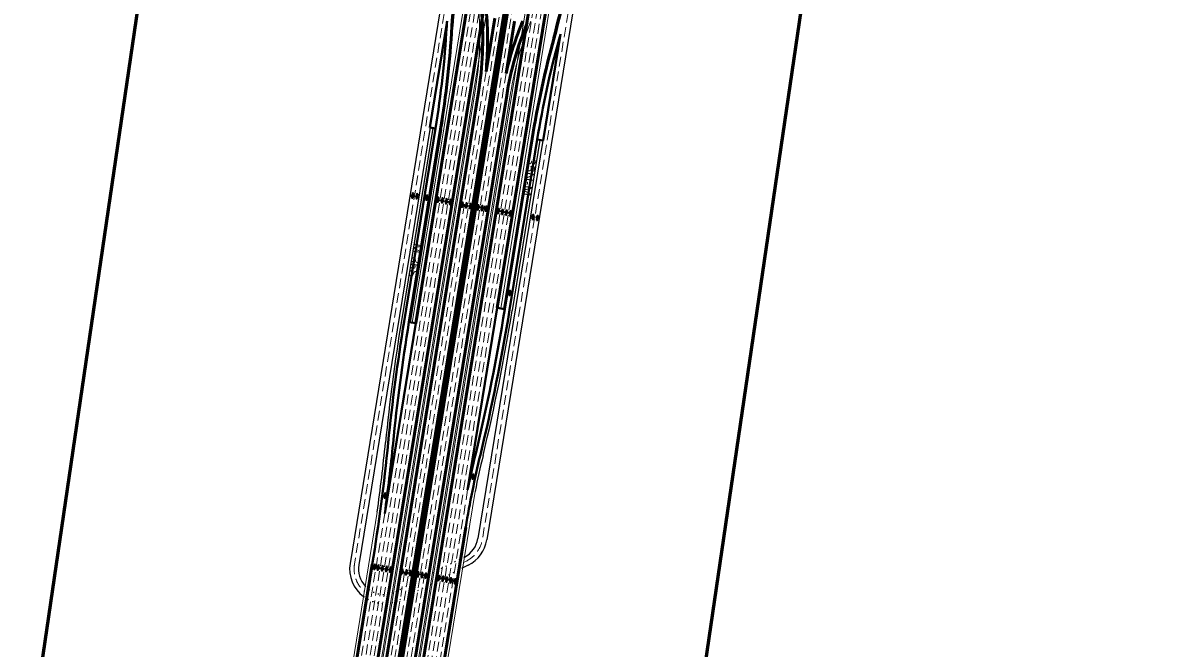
# Model space of a CAD drawing. Extents: x 2329387 to 2347382, y 6951580 to 6987999.
# Drawn here: x 2331839 to 2335155, y 6980657 to 6982469 of the extents above; entities that cross this region are included whole.
import ezdxf

# ---------------------------------------------------------------- set-up
doc = ezdxf.new("R2010")
doc.units = 0
doc.header["$LTSCALE"] = 9.6
doc.linetypes.add('DOTTED', pattern=[1.5, 0.3, -1.2])
doc.linetypes.add('MEDIUM_DASHED', pattern=[4.5, 3, -1.5])
for name, color, linetype, lineweight in [('26', 7, 'Continuous', 53), ('27', 7, 'Continuous', 40), ('28', 7, 'Continuous', 25), ('30', 7, 'Continuous', 13), ('31', 7, 'Continuous', 53), ('41', 7, 'Continuous', 35), ('50', 7, 'MEDIUM_DASHED', 13), ('62', 7, 'Continuous', 60)]:
    doc.layers.add(name, color=color, linetype=linetype, lineweight=lineweight)
doc.layers.add('40', color=7, linetype='Continuous')

msp = doc.modelspace()

# ---------------------------------------------------------------- linework, layer by layer
at = {"layer": '26'}
for p, q in [((2333226.175, 6982836.253), (2332841.664, 6980470.76)), ((2333178.797, 6982843.954), (2332976.382, 6981598.707)), ((2333326.427, 6982642.749), (2332969.98, 6980449.902)), ((2333373.805, 6982635.048), (2333212.588, 6981643.246)), ((2333121.454, 6981007.799), (2333029.203, 6980440.276)), ((2332850.665, 6980900.096), (2332782.442, 6980480.387))]:
    msp.add_line(p, q, dxfattribs=at)
at = {"layer": '26', "lineweight": 13}
for p, q in [((2333236.045, 6982834.649), (2332851.535, 6980469.155)), ((2333168.926, 6982845.559), (2332966.511, 6981600.312)), ((2333316.556, 6982644.353), (2332960.11, 6980451.507)), ((2333383.672, 6982633.418), (2333222.458, 6981641.641)), ((2333148.472, 6981111.689), (2333039.073, 6980438.671)), ((2332865.065, 6981051.01), (2332772.571, 6980481.991))]:
    msp.add_line(p, q, dxfattribs=at)
at = {"layer": '27'}
for p, q in [((2333067.062, 6982474.436), (2333016.95, 6982166.149)), ((2333395.235, 6982436.552), (2333345.123, 6982128.265)), ((2333033.73, 6982163.421), (2332942.822, 6981604.163)), ((2333047.548, 6982161.175), (2332956.641, 6981601.916)), ((2333033.73, 6982163.421), (2333016.95, 6982166.149)), ((2333314.525, 6982133.238), (2333234.303, 6981639.716)), ((2333328.344, 6982130.992), (2333248.122, 6981637.47)), ((2333328.344, 6982130.992), (2333345.123, 6982128.265)), ((2333212.588, 6981643.246), (2333126.823, 6981115.624)), ((2333234.303, 6981639.716), (2333212.588, 6981643.246)), ((2332976.382, 6981598.707), (2332886.827, 6981047.767)), ((2332976.382, 6981598.707), (2332956.641, 6981601.916))]:
    msp.add_line(p, q, dxfattribs=at)
at = {"layer": '27', "lineweight": 25}
for p, q in [((2333025.833, 6982164.705), (2332934.926, 6981605.446)), ((2333051.497, 6982160.533), (2332960.589, 6981601.274)), ((2333310.577, 6982133.88), (2333230.355, 6981640.358)), ((2333336.24, 6982129.709), (2333256.018, 6981636.186))]:
    msp.add_line(p, q, dxfattribs=at)
at = {"layer": '27'}
for centre, radius, start, end in [((2335926.305, 6982296.254), 2850.789, 170.76734, 176.73017), ((2330626.764, 6983173.154), 2850.789, 344.8045, 350.76734), ((2330206.054, 6982623.059), 2864.789, 350.76734, 356.73017), ((2330206.054, 6982623.059), 2878.789, 350.76734, 356.73017), ((2335926.305, 6982296.254), 2864.789, 176.43406, 176.73018), ((2336156.019, 6981671.354), 2878.789, 164.8045, 170.76734), ((2336156.019, 6981671.354), 2864.789, 164.8045, 170.76734), ((2330626.764, 6983173.154), 2864.789, 344.8045, 345.10061), ((2327592.77, 6982556.746), 5715.578, 346.48444, 350.76734), ((2327592.77, 6982556.746), 5729.578, 346.48444, 350.76734), ((2338598.173, 6980684.887), 5729.578, 170.76734, 174.31827), ((2338598.173, 6980684.887), 5715.578, 170.76734, 174.31827), ((2327195.314, 6981819.372), 5729.578, 350.76734, 354.31827), ((2327195.314, 6981819.372), 5743.578, 352.27941, 354.31827), ((2335949.129, 6980548.161), 2864.789, 166.48444, 170.76734), ((2335949.129, 6980548.161), 2878.789, 166.48444, 168.63147)]:
    msp.add_arc(centre, radius, start, end, dxfattribs=at)
at = {"layer": '27', "lineweight": 25}
for centre, radius, start, end in [((2335926.305, 6982296.254), 2846.789, 170.76734, 176.73017), ((2330626.764, 6983173.154), 2846.789, 344.8045, 350.76734), ((2330206.054, 6982623.059), 2882.789, 350.76734, 356.73017), ((2336156.019, 6981671.354), 2882.789, 164.8045, 170.76734), ((2327592.77, 6982556.746), 5737.578, 346.48444, 350.76734), ((2338598.173, 6980684.887), 5737.578, 170.76734, 174.31827), ((2327195.314, 6981819.372), 5721.578, 352.28232, 354.31827), ((2335949.129, 6980548.161), 2856.789, 166.48444, 168.62327)]:
    msp.add_arc(centre, radius, start, end, dxfattribs=at)
at = {"layer": '28'}
for p, q in [((2333094.181, 6982797.091), (2332786.266, 6980902.809)), ((2333471.999, 6982752.984), (2333182.352, 6980971.084)), ((2333017.937, 6982165.988), (2332811.93, 6980898.638)), ((2333344.136, 6982128.425), (2333156.689, 6980975.255)), ((2333128.737, 6980897.871), (2333112.372, 6980889.604))]:
    msp.add_line(p, q, dxfattribs=at)
at = {"layer": '28', "linetype": 'DOTTED'}
for p, q in [((2333117.013, 6980921.077), (2332916.13, 6980819.598)), ((2333112.372, 6980889.604), (2332930.06, 6980797.507)), ((2332918.335, 6980820.713), (2332941.516, 6980832.423))]:
    msp.add_line(p, q, dxfattribs=at)
at = {"layer": '28'}
for centre, radius, start, end in [((2333083.647, 6980987.128), 74, 297.25103, 350.76734), ((2333083.647, 6980987.128), 100, 296.80123, 350.76734), ((2332884.971, 6980886.764), 100, 170.76734, 233.38023), ((2332884.971, 6980886.764), 74, 170.76656, 222.33268)]:
    msp.add_arc(centre, radius, start, end, dxfattribs=at)
at = {"layer": '28', "linetype": 'DOTTED'}
for centre, radius, start, end in [((2333077.645, 6980955.417), 74, 296.80014, 297.25102), ((2332884.971, 6980886.764), 74, 222.33269, 296.79976), ((2332884.971, 6980886.764), 100, 233.38023, 296.80123)]:
    msp.add_arc(centre, radius, start, end, dxfattribs=at)
at = {"layer": '30', "lineweight": 53}
for p, q in [((2333271.366, 6982740.303), (2332900.887, 6980461.133)), ((2333281.236, 6982738.699), (2332910.757, 6980459.529))]:
    msp.add_line(p, q, dxfattribs=at)
at = {"layer": '30'}
for p, q in [((2333275.314, 6982739.661), (2332904.835, 6980460.492)), ((2333277.288, 6982739.341), (2332906.809, 6980460.171))]:
    msp.add_line(p, q, dxfattribs=at)
at = {"layer": '31'}
for p, q in [((2333205.301, 6982483.463), (2333180.043, 6982328.074)), ((2333262.55, 6982474.157), (2333237.926, 6982322.673)), ((2333158.215, 6982268.582), (2332865.353, 6980466.909)), ((2333239.787, 6982259.33), (2332946.291, 6980453.753))]:
    msp.add_line(p, q, dxfattribs=at)
at = {"layer": '31', "lineweight": 13}
for p, q in [((2333149.671, 6982278.347), (2332855.483, 6980468.514)), ((2333251.033, 6982266.189), (2332956.162, 6980452.148))]:
    msp.add_line(p, q, dxfattribs=at)
for centre, radius, start, end in [((2334182.346, 6982106.118), 972.93, 157.63695, 157.63695), ((2332215.009, 6982430.276), 946.93, 350.76734, 4.36603), ((2334185.695, 6982114.26), 946.93, 157.63695, 170.76734)]:
    msp.add_arc(centre, radius, start, end, dxfattribs=at)
at = {"layer": '31'}
for centre, radius, start, end in [((2332215.656, 6982421.795), 954.93, 350.76734, 4.36603), ((2332215.656, 6982421.795), 968.93, 354.44931, 4.36603), ((2334182.346, 6982106.118), 968.93, 157.63695, 167.08536), ((2334182.346, 6982106.118), 954.93, 157.63695, 170.76734)]:
    msp.add_arc(centre, radius, start, end, dxfattribs=at)
at = {"layer": '41'}
for points in [[(2332970.135, 6981975.177), (2332967.179, 6981975.691), (2332966.012, 6981968.985), (2332963.611, 6981969.403), (2332966.1, 6981961.662), (2332971.057, 6981968.108), (2332968.969, 6981968.471)], [(2332982.783, 6981973.463), (2332979.826, 6981973.977), (2332978.66, 6981967.271), (2332976.258, 6981967.689), (2332978.747, 6981959.948), (2332983.704, 6981966.394), (2332981.616, 6981966.757)], [(2333011.015, 6981968.985), (2333008.059, 6981969.5), (2333006.892, 6981962.794), (2333004.491, 6981963.212), (2333006.979, 6981955.47), (2333011.936, 6981961.916), (2333009.848, 6981962.279)], [(2333043.591, 6981962.973), (2333040.635, 6981963.487), (2333039.468, 6981956.781), (2333037.067, 6981957.199), (2333039.555, 6981949.458), (2333044.512, 6981955.904), (2333042.424, 6981956.267)], [(2333055.815, 6981960.975), (2333052.859, 6981961.489), (2333051.692, 6981954.783), (2333049.291, 6981955.201), (2333051.78, 6981947.46), (2333056.737, 6981953.905), (2333054.648, 6981954.269)], [(2333067.734, 6981958.8), (2333064.778, 6981959.315), (2333063.611, 6981952.609), (2333061.21, 6981953.027), (2333063.698, 6981945.285), (2333068.655, 6981951.731), (2333066.567, 6981952.094)], [(2333079.305, 6981956.974), (2333076.349, 6981957.488), (2333075.182, 6981950.782), (2333072.781, 6981951.2), (2333075.269, 6981943.459), (2333080.226, 6981949.905), (2333078.138, 6981950.268)], [(2333113.633, 6981948.572), (2333110.676, 6981949.086), (2333109.51, 6981942.38), (2333107.108, 6981942.798), (2333109.597, 6981935.057), (2333114.554, 6981941.503), (2333112.466, 6981941.866)], [(2333125.812, 6981946.659), (2333122.856, 6981947.173), (2333121.689, 6981940.467), (2333119.288, 6981940.885), (2333121.777, 6981933.143), (2333126.734, 6981939.589), (2333124.646, 6981939.953)], [(2333137.25, 6981944.888), (2333134.293, 6981945.402), (2333133.127, 6981938.696), (2333130.725, 6981939.114), (2333133.214, 6981931.372), (2333138.171, 6981937.818), (2333136.083, 6981938.182)], [(2333154.193, 6981928.285), (2333157.149, 6981927.771), (2333158.316, 6981934.477), (2333160.717, 6981934.059), (2333158.229, 6981941.801), (2333153.272, 6981935.355), (2333155.36, 6981934.991)], [(2333165.817, 6981926.508), (2333168.774, 6981925.994), (2333169.94, 6981932.7), (2333172.342, 6981932.282), (2333169.853, 6981940.023), (2333164.896, 6981933.577), (2333166.984, 6981933.214)], [(2333176.994, 6981924.751), (2333179.951, 6981924.237), (2333181.117, 6981930.942), (2333183.519, 6981930.525), (2333181.03, 6981938.266), (2333176.073, 6981931.82), (2333178.161, 6981931.457)], [(2333213.189, 6981918.142), (2333216.145, 6981917.628), (2333217.312, 6981924.334), (2333219.713, 6981923.916), (2333217.225, 6981931.657), (2333212.268, 6981925.211), (2333214.356, 6981924.848)], [(2333225.095, 6981915.47), (2333228.051, 6981914.956), (2333229.218, 6981921.662), (2333231.619, 6981921.244), (2333229.13, 6981928.985), (2333224.173, 6981922.54), (2333226.262, 6981922.176)], [(2333236.272, 6981913.284), (2333239.228, 6981912.77), (2333240.395, 6981919.476), (2333242.796, 6981919.058), (2333240.307, 6981926.799), (2333235.35, 6981920.353), (2333237.439, 6981919.99)], [(2333248.178, 6981910.855), (2333251.134, 6981910.341), (2333252.301, 6981917.047), (2333254.702, 6981916.629), (2333252.213, 6981924.37), (2333247.256, 6981917.925), (2333249.344, 6981917.561)], [(2333313.097, 6981900.407), (2333316.053, 6981899.893), (2333317.22, 6981906.599), (2333319.621, 6981906.181), (2333317.132, 6981913.922), (2333312.175, 6981907.477), (2333314.263, 6981907.113)], [(2333326.128, 6981898.073), (2333329.084, 6981897.558), (2333330.251, 6981904.264), (2333332.652, 6981903.847), (2333330.163, 6981911.588), (2333325.206, 6981905.142), (2333327.295, 6981904.779)], [(2333246.229, 6981680.671), (2333249.185, 6981680.157), (2333250.352, 6981686.863), (2333252.753, 6981686.445), (2333250.264, 6981694.187), (2333245.307, 6981687.741), (2333247.395, 6981687.377)], [(2333139.04, 6981148.237), (2333141.949, 6981147.497), (2333143.626, 6981154.094), (2333145.988, 6981153.493), (2333144.101, 6981161.402), (2333138.664, 6981155.356), (2333140.718, 6981154.833)], [(2332890.091, 6981105.637), (2332887.135, 6981106.152), (2332885.968, 6981099.446), (2332883.567, 6981099.863), (2332886.056, 6981092.122), (2332891.013, 6981098.568), (2332888.925, 6981098.931)], [(2332859.671, 6980899.006), (2332856.715, 6980899.52), (2332855.548, 6980892.814), (2332853.147, 6980893.232), (2332855.635, 6980885.491), (2332860.593, 6980891.936), (2332858.504, 6980892.3)], [(2332870.143, 6980897.057), (2332867.186, 6980897.572), (2332866.02, 6980890.866), (2332863.618, 6980891.283), (2332866.107, 6980883.542), (2332871.064, 6980889.988), (2332868.976, 6980890.351)], [(2332882.367, 6980895.059), (2332879.411, 6980895.573), (2332878.244, 6980888.867), (2332875.843, 6980889.285), (2332878.331, 6980881.544), (2332883.288, 6980887.99), (2332881.2, 6980888.353)], [(2332894.286, 6980892.885), (2332891.329, 6980893.399), (2332890.163, 6980886.693), (2332887.761, 6980887.111), (2332890.25, 6980879.37), (2332895.207, 6980885.816), (2332893.119, 6980886.179)], [(2332905.857, 6980891.058), (2332902.9, 6980891.573), (2332901.734, 6980884.867), (2332899.332, 6980885.285), (2332901.821, 6980877.543), (2332906.778, 6980883.989), (2332904.69, 6980884.352)], [(2332939.719, 6980884.857), (2332936.763, 6980885.372), (2332935.596, 6980878.666), (2332933.195, 6980879.084), (2332935.683, 6980871.342), (2332940.64, 6980877.788), (2332938.552, 6980878.151)], [(2332951.899, 6980882.944), (2332948.943, 6980883.458), (2332947.776, 6980876.752), (2332945.375, 6980877.17), (2332947.863, 6980869.429), (2332952.82, 6980875.875), (2332950.732, 6980876.238)], [(2332963.336, 6980881.173), (2332960.38, 6980881.687), (2332959.213, 6980874.981), (2332956.812, 6980875.399), (2332959.3, 6980867.658), (2332964.257, 6980874.104), (2332962.169, 6980874.467)], [(2332980.279, 6980864.571), (2332983.236, 6980864.056), (2332984.403, 6980870.762), (2332986.804, 6980870.345), (2332984.315, 6980878.086), (2332979.358, 6980871.64), (2332981.446, 6980871.277)], [(2332991.904, 6980862.793), (2332994.86, 6980862.279), (2332996.027, 6980868.985), (2332998.428, 6980868.567), (2332995.939, 6980876.308), (2332990.982, 6980869.863), (2332993.071, 6980869.499)], [(2333003.081, 6980861.036), (2333006.037, 6980860.522), (2333007.204, 6980867.228), (2333009.605, 6980866.81), (2333007.116, 6980874.551), (2333002.159, 6980868.106), (2333004.247, 6980867.742)], [(2333040.482, 6980854.592), (2333043.438, 6980854.078), (2333044.605, 6980860.784), (2333047.006, 6980860.366), (2333044.517, 6980868.107), (2333039.56, 6980861.661), (2333041.648, 6980861.298)], [(2333052.388, 6980851.92), (2333055.344, 6980851.406), (2333056.511, 6980858.112), (2333058.912, 6980857.694), (2333056.423, 6980865.435), (2333051.466, 6980858.99), (2333053.554, 6980858.626)], [(2333063.565, 6980849.734), (2333066.521, 6980849.22), (2333067.688, 6980855.926), (2333070.089, 6980855.508), (2333067.6, 6980863.249), (2333062.643, 6980856.804), (2333064.731, 6980856.44)], [(2333075.47, 6980847.305), (2333078.427, 6980846.791), (2333079.593, 6980853.497), (2333081.995, 6980853.079), (2333079.506, 6980860.821), (2333074.549, 6980854.375), (2333076.637, 6980854.011)], [(2333087.376, 6980844.876), (2333090.333, 6980844.362), (2333091.499, 6980851.068), (2333093.901, 6980850.65), (2333091.412, 6980858.392), (2333086.455, 6980851.946), (2333088.543, 6980851.582)]]:
    msp.add_lwpolyline(points, close=True, dxfattribs=at)
at = {"layer": '50'}
for p, q in [((2333486.921, 6982925.807), (2333169.52, 6980973.17)), ((2333190.641, 6982842.029), (2332806.131, 6980476.536)), ((2333202.486, 6982840.104), (2332817.975, 6980474.611)), ((2333214.33, 6982838.178), (2332829.82, 6980472.685)), ((2333107.013, 6982795.006), (2332799.098, 6980900.723)), ((2333259.521, 6982742.229), (2332889.042, 6980463.059)), ((2333293.081, 6982736.773), (2332922.602, 6980457.604)), ((2333338.271, 6982640.824), (2332981.825, 6980447.977)), ((2333350.116, 6982638.898), (2332993.669, 6980446.052)), ((2333361.961, 6982636.973), (2333005.514, 6980444.126)), ((2333180.043, 6982328.074), (2332877.198, 6980464.984)), ((2333237.926, 6982322.673), (2332934.447, 6980455.678)), ((2333126.823, 6981115.624), (2333017.358, 6980442.201)), ((2332886.827, 6981047.767), (2332794.286, 6980478.461)), ((2333123.393, 6980909.735), (2333114.952, 6980905.471))]:
    msp.add_line(p, q, dxfattribs=at)
for centre, start, end in [((2333083.647, 6980987.128), 296.80123, 350.76734), ((2332884.971, 6980886.764), 170.76734, 228.84727)]:
    msp.add_arc(centre, 87, start, end, dxfattribs=at)
at = {"layer": '62'}
msp.add_lwpolyline([(2334855.87, 6987723.712), (2333675.66, 6979665.287), (2331838.812, 6980234.901), (2332975.924, 6987999.043)], close=True, dxfattribs=at)

# ---------------------------------------------------------------- texts
at = {"layer": '40'}
for s, rotation, width, p in [('35N-M', 261.862, 1.15, (2333301.296, 6982079.235)), ('M-35S', 260.862, 1.05, (2332971.442, 6981831.522))]:
    msp.add_text(s, height=24, rotation=rotation, dxfattribs=dict(at, width=width)).set_placement(p)

doc.saveas('drawing.dxf')
